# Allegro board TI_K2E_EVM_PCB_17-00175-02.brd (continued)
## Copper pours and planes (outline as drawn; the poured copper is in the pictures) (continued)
GND on TOP: 173.58,51.54 174.04,51.08 174.04,49.23 173.6,48.79 170.77,48.79 170.38,49.17 170.38,51.23 170.69,51.54
GND on TOP: 130.68,17.35 130.68,12.75 135.25,12.75 135.25,17.35
GND on TOP: 135.64,57.23 135.24,57.62 135.24,59.68 135.25,59.69 135.25,62.38 136.04,63.17 159.66,63.17 159.92,62.92 159.92,60.58 159.72,60.38 153.8,60.38 152.49,61.68 144.73,61.68 144.59,61.82 143.66,61.82 143.52,61.68 139.56,61.68 139.19,61.32 139.19,60.07 139.55,59.72 141.05,59.72 141.12,59.64 141.12,57.71 141.1,57.68 140.71,57.68 140.25,57.23
GND on TOP: 175.81,31.86 175.81,33.26 175.68,33.39 173.9,33.39 173.63,33.12 173.63,31.93 173.82,31.74 175.68,31.74
GND on TOP: 124.21,100.14 124.21,97.14 124.37,96.98 125.34,96.98 125.66,97.3 125.66,100.13 125.43,100.36 124.42,100.36
GND on TOP: 168,53.57 170.18,53.57 171.5,54.89 171.5,54.97 171.81,55.27 172.69,55.27 172.9,55.07 172.9,53.34 171.68,52.12 170.18,52.12 169.29,51.23 169.29,50.06 169.04,49.81 165.79,49.81 165.48,50.11 165.48,50.98 165.6,51.09 167.14,51.09 167.74,51.69 167.74,53.31
GND on TOP: 39.24,9.02 41.35,9.02 41.78,8.59 41.78,2.54 41.27,2.03 31.24,2.03 30.48,2.79 30.48,8.26 30.61,8.38 38.61,8.38
GND on TOP: 48.51,31.24 47.37,31.24 47.12,31.5 47.12,33.15 47.37,33.4 48.39,33.4 48.64,33.15 48.64,31.37
GND on TOP: 157.96,68.05 157.66,68.35 157.66,69.8 157.96,70.1 158.22,70.1 158.53,70.41 163.14,70.41 163.54,70.02 163.54,64.79 162.88,64.14 138.05,64.14 137.67,64.52 137.67,66.67 137.79,66.8 144.27,66.8 145.29,65.79 159.46,65.79 159.61,65.94 159.61,67.61 159.18,68.05
GND on TOP: 42.42,30.35 41.15,30.35 40.84,30.66 40.84,32.72 41.27,33.15 42.29,33.15 42.55,32.89 42.55,30.48
GND on TOP: 108.48,121.87 108.61,122 108.61,122.33 108.46,122.48 107.52,122.48 107.31,122.68 106.93,122.68 106.81,122.56 106.81,121.55 106.93,121.43 107.29,121.43 107.73,121.87
GND on TOP: 158.37,34.65 158.37,31.7 158.57,31.5 161.8,31.5 162.79,32.49 162.79,34.06 163.08,34.35 163.08,35.17 163.02,35.23 158.95,35.23
GND on BOTTOM: 127.38,8.89 127.38,4.45 127.13,4.19 125.73,4.19 125.48,4.45 125.48,8.76 125.73,9.02 127.25,9.02
GND on BOTTOM: 28.96,68.83 25.4,68.83 25.27,68.96 25.27,70.23 25.53,70.48 29.21,70.48 29.44,70.26 29.44,69.32
GND on BOTTOM: 77.88,33.4 79.12,33.4 79.25,33.27 79.25,31.34 79.22,31.32 79.6,30.94 80.19,30.94 80.49,30.63 80.49,29.44 80.24,29.18 78.11,29.18 77.72,29.57 77.72,33.25
GND on BOTTOM: 49.07,39.34 50.6,39.34 50.88,39.06 50.88,37.85 50.7,37.67 47.85,37.67 47.78,37.74 47.78,39.24 47.88,39.34 49.07,39.34
GND on BOTTOM: 114.3,32.36 115.9,32.36 116.1,32.56 116.94,32.56 117.17,32.33 117.17,30.99 116.94,30.76 114.33,30.76 114.07,31.01 114.07,32.13
GND on BOTTOM: 98.45,15.27 98.45,9.78 103.1,9.78 103.1,15.27
GND on BOTTOM: 147.24,32.92 147.68,32.49 147.68,31.57 147.42,31.32 141.22,31.32 141.12,31.42 141.12,32.64 141.4,32.92
GND on BOTTOM: 63.2,11.43 63.2,6.1 66.4,6.1 66.4,11.43
GND on BOTTOM: 120.29,31.67 118.11,31.67 117.91,31.47 117.91,30.73 118.21,30.43 120.14,30.43 120.42,30.71 120.42,31.55
GND on BOTTOM: 129.41,32.38 129.41,28.22 129.01,27.81 127.69,27.81 127.53,27.97 127.53,32.08 127.94,32.49 129.31,32.49
GND on BOTTOM: 151.49,26.67 151.49,26.11 151.69,25.91 155.45,25.91 155.6,26.06 155.6,26.67 155.35,26.92 151.74,26.92
GND on BOTTOM: 29.95,75.95 31.14,75.95 31.52,75.56 31.52,74.22 31.42,74.12 29.72,74.12 29.67,74.17 29.67,75.67
GND on BOTTOM: 30.99,71.04 29.49,71.04 29.26,71.27 29.26,72.62 29.36,72.72 31.06,72.72 31.12,72.67 31.11,71.17
GND on BOTTOM: 135.7,99.88 139.85,99.88 139.92,99.95 139.92,100.95 139.8,101.06 138.84,101.06 138.08,101.82 135.56,101.82 135.55,101.83 135.31,101.83 135.24,101.75 135.24,100.35
GND on BOTTOM: 176.45,106.55 174.98,106.55 174.7,106.83 174.7,107.26 174.85,107.42 176.53,107.42 176.66,107.29 176.66,106.76
GND on BOTTOM: 47.73,81.56 47.73,82.78 47.6,82.91 47.6,83.74 47.85,84 49.12,84 49.28,83.85 49.28,81.28 49.15,81.15 48.13,81.15
GND on BOTTOM: 54.15,3.38 54.15,1.8 53.9,1.55 52.35,1.55 51.54,2.36 51.54,3.15 51.66,3.28 52.07,3.28 52.53,3.73 52.53,5.23 53.14,5.84 58.04,5.84 58.19,5.69 58.19,4.19 57.71,3.71 57.71,3.51 57.63,3.43 56.97,3.43 56.9,3.51 56.9,3.84 57.23,4.17 57.23,4.67 57.02,4.88 56.69,4.88 56.54,4.72 56.54,4.5 56.44,4.39 55.17,4.39
GND on BOTTOM: 117.09,36.98 117.54,37.43 118.81,37.43 119,37.62 120.4,37.62 120.78,38 120.78,38.51 120.65,38.63 120.65,40.79 120.4,41.05 117.35,41.05 116.23,39.93 109.37,39.93 109.09,39.65 109.09,37.36 109.47,36.98
GND on BOTTOM: 142.44,58.12 142.44,56.13 144.42,56.13 144.42,58.12
GND on BOTTOM: 154.31,71.53 154.31,69.49 156.36,69.49 156.36,71.53
GND on BOTTOM: 100.61,25.86 100.77,25.69 100.77,24.63 100.66,24.51 97.13,24.51 96.93,24.71 96.93,25.73 97.05,25.86
GND on BOTTOM: 82.25,96.93 82.25,92.81 86.36,92.81 86.36,96.93
GND on BOTTOM: 147.75,38.56 147.85,38.66 147.85,39.67 147.75,39.78 144.7,39.78 144.6,39.67 144.6,38.66 144.7,38.56
GND on BOTTOM: 25.65,79.48 25.65,80.85 25.76,80.95 26.7,80.95 26.85,80.8 26.85,79.5 26.7,79.35 25.78,79.35
GND on BOTTOM: 27.61,77.22 28.85,77.22 29.03,77.04 29.03,75.87 28.78,75.62 27.69,75.62 25.91,75.62 25.58,75.95 25.58,77.32 25.6,77.34 25.68,77.34 25.81,77.22
GND on BOTTOM: 111.91,25.86 112.08,25.69 112.08,24.63 111.96,24.51 108.43,24.51 108.23,24.71 108.23,25.73 108.36,25.86
GND on BOTTOM: 124.21,32.89 123.67,33.43 122.76,33.43 122.73,33.4 122.73,31.01 122.99,30.76 126.11,30.76 126.26,30.91 126.26,32.77 126.14,32.89
GND on BOTTOM: 143.28,82.02 143.28,80.29 145.01,80.29 145.01,82.02
GND on BOTTOM: 149.99,15.62 149.99,14.2 150.22,13.97 153.87,13.97 154.05,14.15 154.05,15.62 153.92,15.75 150.11,15.75
GND on BOTTOM: 18.57,60.17 15.8,60.17 15.75,60.22 15.75,61.49 15.95,61.7 17.48,61.7 17.75,61.98 18.47,61.98 18.9,61.54 18.9,60.5
GND on BOTTOM: 111.12,49.07 110.57,49.07 110.24,49.4 110.24,64.14 110.52,64.41 111.33,64.41 111.76,63.98 111.76,54.05 111.56,53.85 111.56,49.83 111.3,49.58 111.3,49.25
GND on BOTTOM: 149.22,89.41 149.45,89.18 149.86,89.18 149.96,89.28 149.96,94.77 149.81,94.92 149.4,94.92 149.22,94.74
GND on BOTTOM: 143.38,14.99 143.51,14.86 144.65,14.86 144.78,14.99 144.78,18.03 144.65,18.16 142.75,18.16 142.62,18.03 142.62,16.38 142.24,16 141.35,16 141.05,15.7 139.67,15.7 139.57,15.6 139.57,15.04 139.62,14.99
GND on BOTTOM: 25.43,22.25 18.26,22.25 17.65,22.86 17.65,24 17.91,24.26 23.11,24.26 23.24,24.13 25.65,24.13 26.16,23.62 26.16,22.99
GND on BOTTOM: 112.7,131.7 112.7,126.7 117.91,126.7 117.91,131.7
GND on BOTTOM: 31.01,80.87 31.01,79.81 30.96,79.76 29.01,79.76 28.73,80.04 28.73,80.92 29.08,81.28 30.61,81.28
GND on BOTTOM: 145.69,19.3 144.3,19.3 142.57,21.03 141.53,21.03 140.49,22.07 139.04,22.07 138.84,22.28 138.84,23.04 139.01,23.22 140.39,23.22 140.97,22.63 144.3,22.63 144.5,22.83 144.5,25.1 144.63,25.22 145.8,25.22 145.85,25.17 145.85,22.07 145.97,21.95 145.97,19.58
GND on BOTTOM: 23.01,19.05 20.7,19.05 20.07,19.68 17.65,19.68 17.4,19.94 17.4,21.21 17.91,21.72 22.61,21.72 25.57,18.76 29.78,18.76 29.92,18.62 29.92,16.89 29.79,16.76 26.8,16.76 26.16,17.4 24.38,17.4 23.75,18.03 23.75,18.31
GND on BOTTOM: 141.43,10.9 141.43,9.37 141.76,9.04 147.22,9.04 147.47,9.3 147.47,9.6 147.83,9.96 148.49,9.96 148.64,10.11 148.64,10.82 148.54,10.92 147.42,10.92 147.02,10.52 145.75,10.52 145.24,11.02 141.55,11.02
GND on BOTTOM: 61.37,29.29 57.2,29.29 56.77,29.72 56.77,35.84 57.12,36.2 61.67,36.2 61.82,36.04 61.82,29.74
GND on BOTTOM: 136.49,89.52 136.38,89.62 131.74,89.62 131.74,89.62 130.75,89.62 130.7,89.57 130.7,88.19 130.76,88.13 135.95,88.13 136.48,88.66 136.48,89.51
GND on BOTTOM, L3_SIG1, L5_SIG2, L8_SIG3, L10_SIG4: 64.36,96.93 64.36,92.81 68.48,92.81 68.48,96.93
GND on L2_GND1: outline of 106 points within 1.02,1.02 179.58,147.48
GND on L5_SIG2: 82.25,96.93 82.25,93.4 82.83,92.81 86.36,92.81 86.36,96.93
GND on L6_GND2: outline of 106 points within 1.02,1.02 179.58,147.48
GND on L7_GND3: outline of 106 points within 1.02,1.02 179.58,147.48
GND on L8_SIG3: 101.65,1.02 101.65,1.75 102.13,2.24 102.13,6.22 102.31,6.4 104.67,6.4 106.55,4.52 106.55,1.85 105.72,1.02
GND on L11_GND4: outline of 106 points within 1.02,1.02 179.58,147.48
GND_3 on TOP: 107.56,123.08 107.72,122.91 108.69,122.91 108.9,123.13 108.9,124.02 108.73,124.19 107.69,124.19 107.56,124.05
GND_LAN on TOP: 176.25,33.35 176.45,33.55 178.59,33.55 179.02,33.12 179.02,11.28 179.01,11.26 179.01,9.41 178.66,9.07 173.79,9.07 173.08,9.78 173.08,12.22 173.99,13.13 173.99,27.43 173.1,28.32 173.1,30.81 173.46,31.17 176.05,31.17 176.25,31.37
GND_LAN on L8_SIG3: 154.74,30.25 175.18,30.25 176.17,29.26 176.17,8.59 175.87,8.28 154,8.28 151.61,10.67 151.61,18.41 152.27,19.08 152.27,27.79
GND_USB on BOTTOM: 172.52,141.2 172.69,141.02 174.8,141.02 175.01,140.82 175.01,131.22 175.16,131.06 179.27,131.06 179.53,131.32 179.53,141.66 178.99,142.19 173.66,142.19 173.43,142.42 172.62,142.42 172.52,142.32
VCC0V75 on TOP: 107.9,26.01 95.28,26.01 95,26.29 95,28.12 96.6,29.72 103.93,29.72 104.25,29.41 107.81,29.41 108.48,28.73 108.48,26.59
VCC0V75 on BOTTOM: 95.12,26.26 95,26.39 95,29.82 95.25,30.07 106.4,30.07 108.28,31.95 108.28,35.92 108.66,36.3 117.14,36.3 117.22,36.22 117.22,35.59 117.36,35.45 117.46,35.45 117.5,35.41 118.82,35.41 118.92,35.31 118.92,35.1 118.82,35 117.37,35 117.26,34.89 113.09,34.89 112.65,34.44 112.65,26.44 112.47,26.26
VCC0V75REF on BOTTOM: 122.2,38.53 122.2,36.25 122.07,36.12 121.06,36.12 120.93,36.25 120.93,37.64 121.18,37.9 121.18,41.33 121.44,41.58 123.09,41.58 123.34,41.33 123.34,39.04 123.09,38.79 122.45,38.79
VCC0V85 on TOP (solid shape): 124.28,21.64 124.28,19.1 124.02,18.84 107.15,18.84 106.81,19.18 106.81,21.84 107.34,22.38 123.55,22.38
VCC0V85 on BOTTOM: 34.14,52.76 32.13,52.76 32.03,52.86 32.03,55.65 32.21,55.83 34.11,55.83 34.26,55.68 34.26,52.88
VCC0V85 on BOTTOM: 28.93,81.94 28.7,82.17 28.7,82.8 29.08,83.19 31.95,83.19 32.36,82.78 32.36,81.92 32.23,81.79 31.75,81.79 31.6,81.94
VCC0V85 on L9_PWR2: 124.92,18.24 124.92,13.94 123.95,12.98 119.99,12.98 115.87,17.09 81.48,17.09 80.7,16.31 80.7,11.61 79.64,10.55 69.74,10.55 69.19,11.1 69.19,15.27 68.28,16.18 29.82,16.18 28.96,17.04 28.96,53.49 24.61,57.84 24.61,80.05 27.37,82.82 29.2,82.82 29.85,82.18 29.85,79.12 29.84,79.12 29.84,75.56 28.32,74.04 28.32,59.78 29.57,58.52 35.36,58.52 37.34,56.54 37.34,55.12 35.23,53.01 32.18,53.01 31.62,52.45 31.62,47.37 32.45,46.55 38.8,46.55 40.39,44.96 40.39,40.89 42.04,39.24 45.34,39.24 45.87,38.71 45.87,25.81 49.71,21.97 55.88,21.97 56.26,21.59 56.97,21.59 57.35,21.97 75.23,21.97 80.64,27.38 129.34,27.38 130.33,26.39 130.33,23.65
VCC1V5 on TOP: 146.94,67.69 142.24,67.69 142.11,67.56 138.3,67.56 137.79,68.07 137.79,71.88 138.18,72.26 146.99,72.26 147.04,72.21 147.04,67.79
VCC1V5 on BOTTOM: 109.37,50.01 109.37,61.37 109.12,61.62 109.12,62.56 109.37,62.81 109.37,64.77 109.14,65 107.31,65 107.09,64.77 107.09,59.59 107.67,59 107.67,58.04 107.09,57.45 107.09,50.09 107.29,49.89 109.25,49.89
VCC1V5 on BOTTOM: 116.81,32.92 117.13,33.24 117.12,33.25 117.12,34.29 116.97,34.44 113.21,34.44 113.08,34.31 113.08,32.74 113.16,32.66 113.92,32.66 114.17,32.92
VCC1V5 on L9_PWR2: 78.71,28.4 76.4,30.71 76.4,38.18 69.9,44.68 69.9,52.02 69.72,52.2 69.42,52.2 69.37,52.25 69.37,69.7 69.44,69.77 69.7,69.77 69.9,69.98 69.9,74.37 69.55,74.72 69.55,76.6 72.82,79.88 72.82,82.02 73.58,82.78 77.19,82.78 78.36,83.95 87.76,83.95 91.69,87.88 91.69,88.77 93.47,90.55 93.47,92.33 94.23,93.09 131.06,93.09 135.89,88.27 135.89,76.58 137.54,74.93 139.95,74.93 140.59,74.3 140.59,58.55 140.34,58.29 130.05,58.29 128.78,57.02 128.78,37.72 130.56,35.94 130.56,28.83 130.12,28.4
VCC1V8 on TOP (solid shape): 124.08,6.99 124.08,5.01 123.88,4.8 107.46,4.8 107.31,4.95 107.31,6.83 107.41,6.92 112.47,6.92 112.76,7.21 123.85,7.21
VCC1V8 on TOP: 159.56,50.9 160.48,50.9 160.6,51.03 160.6,52.22 160.48,52.35 159.46,52.35 158.97,51.85 157.34,51.85 157.15,51.66 157.15,50.22 157.23,50.14 157.78,50.14 157.91,50.27 157.91,50.95 158.1,51.14 159.32,51.14
VCC1V8 on TOP: 49.02,33.91 45.21,33.91 45.09,34.04 45.09,35.13 45.36,35.41 48.97,35.41 49.15,35.23 49.15,34.04
VCC1V8 on TOP: 152.45,35.56 150.75,35.56 150.62,35.69 150.62,37.08 150.83,37.29 151.99,37.29 152.17,37.47 152.53,37.47 152.73,37.26 152.73,35.84
VCC1V8 on BOTTOM: 151,19.81 149.73,19.81 149.61,19.94 149.61,21.21 149.86,21.46 150.88,21.46 151.13,21.21 151.13,19.94
VCC1V8 on BOTTOM: 31.8,70.38 31.93,70.51 33.05,70.51 33.12,70.43 33.12,68.99 32.84,68.71 30.25,68.71 29.92,69.04 29.92,70.21 30.1,70.38 31.7,70.38
VCC1V8 on BOTTOM: 50.67,40.13 50.9,40.36 50.9,41.78 50.77,41.91 48.39,41.91 47.6,41.12 47.6,40.41 47.88,40.13
VCC1V8 on BOTTOM: 32.31,59.18 34.04,59.18 34.29,58.93 34.29,56.31 34.11,56.13 32.21,56.13 32.05,56.29 32.05,58.93
VCC1V8 on BOTTOM: 75.01,83.97 73.89,82.85 73.05,82.85 72.87,83.03 72.87,83.52 73.48,84.12 73.48,84.63 75.36,86.51 77.14,86.51 77.32,86.33 77.32,84.53 76.76,83.97
VCC1V8 on BOTTOM: 81.15,62.2 81.15,63.53 81.43,63.81 82.96,63.8 83.08,63.68 83.08,62.15 82.96,62.03 81.33,62.03
VCC1V8 on L5_SIG2: 18.75,81.71 19.68,82.65 23.29,82.65 23.75,82.19 23.75,81.71 23.01,80.98 23.01,79.2 23.9,78.31 29.84,78.31 30.19,77.97 30.19,77.15 31.17,76.17 31.17,70.05 31.7,69.52 31.7,65.56 30.84,64.69 30.84,58.93 31.65,58.12 33.71,58.12 34.44,57.38 34.44,55.19 36.53,53.11 44.32,53.11 46.05,51.38 46.05,37.19 47.68,35.56 49.35,35.56 56.06,28.85 72.8,28.85 77.42,24.23 77.42,9.78 77.69,9.51 78.4,9.51 79.97,11.09 79.97,13.88 81.64,15.54 81.64,17.75 82.96,19.08 105.28,19.08 108.46,22.25 119.1,22.25 124.87,28.02 124.87,35.59 125.98,36.7 125.98,46.33 130.92,51.27 149.52,51.27 150.55,52.3 157.91,52.3 158.52,51.69 158.52,40.67 152.58,34.72 152.58,20.73 152.54,20.69 152.54,11.32 143.05,1.83 118.19,1.83 117.98,2.03 117.98,3.43 117.63,3.78 114.66,3.78 114.38,3.51 114.38,2.11 114.1,1.83 30.91,1.83 28.98,3.76 28.98,7.11 27.71,8.38 23.9,8.38 21.97,10.31 21.97,12.85 19.99,14.83 19.99,26.31 18.75,27.56
VCC1V8 on L5_SIG2: 84.2,61.39 81.43,61.39 80.85,61.98 80.85,64.36 81.61,65.13 81.61,69.6 79.98,71.22 78.94,71.22 73.1,77.06 73.1,84.89 74.83,86.61 77.17,86.61 84.02,79.76 84.02,66.85 84.38,66.5 84.38,61.57
VCC1V8 on L8_SIG3: 69.01,69.14 66.09,69.14 65.94,69.29 65.94,76.2 67.54,77.8 69.49,77.8 71.65,79.96 72.72,79.96 73.41,80.64 73.41,82.12 73.69,82.4 76.28,82.4 76.4,82.27 76.4,81.53 73.79,78.92 72.19,78.92 69.27,76 69.27,69.39
VCC1V8 on L9_PWR2: 73.15,83.19 73.03,83.31 73.03,87.5 71.37,89.15 56.21,89.15 54.64,87.58 53.21,87.58 51.77,89.03 49.28,89.03 48.95,89.36 48.95,92.79 48.13,93.6 44.91,93.6 43.18,91.87 43.18,87.6 43.31,87.73 43.31,81.13 50.69,73.75 50.69,73.75 51.62,72.81 51.62,67.41 51.49,67.28 48.53,67.28 46.94,65.69 43.19,65.69 39.77,69.11 32.49,69.11 31.37,68 29.57,68 28.73,68.83 28.73,73.78 30.15,75.21 30.15,82.38 29.43,83.1 26.97,83.1 26.02,84.05 26.02,89.89 25.12,90.8 8.57,90.8 7.72,91.65 7.72,140.46 14.25,146.99 164.92,146.99 166.13,145.78 170.07,145.78 171.42,144.42 171.42,141.07 174.45,138.05 174.45,119.18 172.11,116.84 131.06,116.84 125.6,111.38 125.6,94.61 124.84,93.85 94.36,93.85 92.96,92.46 92.96,90.93 91.31,89.28 91.31,88.27 87.63,84.58 78.11,84.58 76.71,83.19
VCC1V8 on L10_SIG4: outline of 100 points within 25.4,25.43 134.52,78.66
VCC2V5 on TOP: 128.88,14.1 127.43,14.1 125.09,16.43 125.09,39.7 128.45,43.05 136.53,43.05 136.98,42.6 136.98,41.76 136.63,41.4 132,41.4 130.86,40.26 130.86,28.96 131.32,28.5 140.84,28.5 143.36,25.98 143.36,24.05 137.79,18.49 131.06,18.49 129.31,16.74 129.31,14.53
VCC2V5 on BOTTOM: 144.12,23.11 144.17,23.16 144.17,23.65 144.07,23.75 142.6,23.75 141.3,25.04 138.4,25.04 138.13,24.77 138.13,23.83 138.38,23.57 138.79,23.57 139.14,23.93 140.23,23.93 141.05,23.11
VCC2V5 on L3_SIG1: 148.18,8.03 144.35,11.86 144.35,16.71 141.94,19.13 139.93,19.13 138.18,20.88 138.18,24.97 138.28,25.07 149.53,25.07 155.14,30.68 170.41,30.68 173.99,27.1 173.99,23.85 173.46,23.32 168.96,23.32 167.56,21.92 167.56,17.63 168.2,16.99 173.33,16.99 173.91,16.41 173.91,8.28 173.66,8.03
VCC3_LCDBK on BOTTOM (solid shape): 84.82,144.42 84.82,140.25 84.25,139.67 82.19,139.67 81.75,140.12 81.75,144.55 82.21,145.01 84.24,145.01
VCC3V3_AUX on TOP: 79.12,1.14 78.74,1.52 78.74,2.79 79.38,3.43 81.53,3.43 82.3,2.67 89.03,2.67 89.69,3.33 89.69,6.78 89.76,6.86 94.64,6.86 94.84,6.65 94.84,1.88 94.11,1.14
VCC3V3_AUX on BOTTOM: 25.15,80.8 25.15,79.22 25.27,79.09 25.27,77.67 25.2,77.6 24.08,77.6 23.95,77.72 23.95,80.72 24.16,80.92 25.02,80.92
VCC3V3_AUX on BOTTOM: 82.19,138.91 84.15,138.91 84.48,138.58 84.48,136.91 84.28,136.7 82.25,136.7 82.04,136.91 82.04,138.76
VCC3V3_AUX on BOTTOM: 123.69,34.68 123.34,34.34 121.01,34.34 120.9,34.24 120.9,34.16 121.18,33.88 124.1,33.88 124.41,33.58 125.98,33.58 126.29,33.88 126.29,35.76 126.11,35.94 123.77,35.94 123.69,35.85
VCC3V3_AUX on BOTTOM: 72.82,89.59 74.12,89.59 74.42,89.89 74.42,91.06 74.17,91.31 72.9,91.31 72.77,91.19 72.77,89.64
VCC3V3_AUX on BOTTOM: 90.93,100.97 90.93,99.75 90.7,99.52 88.8,99.52 88.6,99.72 88.6,100.97 88.77,101.14 90.75,101.14
VCC3V3_AUX on BOTTOM: 148.06,19.13 146.91,19.13 146.43,19.61 146.43,23.14 146.15,23.42 146.15,23.65 146.25,23.75 148.16,23.75 148.41,23.5 148.41,19.48
VCC3V3_AUX on BOTTOM: 147.07,13.97 147.07,12.95 147.19,12.83 147.83,12.83 147.96,12.95 147.96,13.97 147.83,14.1 147.19,14.1
VCC3V3_AUX on L4_PWR1: outline of 155 points within 7.85,1.02 179.4,146.94
VCC3V3_AUX on L5_SIG2: 15.44,1.19 12.32,1.19 11.94,1.57 11.94,4.37 10.85,5.46 2.16,5.46 1.45,6.17 1.45,66.55 2.46,67.56 11.56,67.56 12.22,68.22 12.22,84.86 12.88,85.52 26.52,85.52 27.43,84.61 27.43,79.58 26.87,79.02 24.08,79.02 23.62,79.48 23.62,80.64 24.26,81.28 24.26,82.6 23.65,83.21 19.13,83.21 17.65,81.74 17.65,15.54 21.34,11.86 21.34,9.07 19.91,7.65 15.7,7.65 15.62,7.57 15.62,1.37
VCC3V3_AUX_F1 on BOTTOM: 90.88,97.23 90.73,97.08 88.09,97.08 87.71,97.46 87.71,97.87 87.1,98.48 81.08,98.48 80.72,98.12 80.72,91.74 81.1,91.36 87.25,91.36 87.68,91.8 87.68,96.82 87.76,96.9 88.85,96.9 88.98,96.77 88.98,91.54 87.58,90.14 86.44,90.14 85.98,90.6 84.2,90.6 83.77,90.17 80.37,90.17 79.38,91.16 79.38,94.67 80.21,95.5 80.21,99.03 80.37,99.19 88.09,99.19 88.77,98.5 90.78,98.5 90.88,98.4
VCC3V3_AUX_F2 on BOTTOM: 71.37,89.28 69.62,89.28 68.88,90.02 62.61,90.02 61.32,91.31 61.32,95.73 62,96.42 62,98.86 62.87,99.72 64.01,99.72 64.14,99.59 64.14,98.53 64.01,98.4 63.27,98.4 62.66,97.79 62.66,91.82 63.12,91.36 69.62,91.36 69.75,91.49 69.75,98.81 69.88,98.93 71.2,98.93 71.22,98.91 71.22,94.31 71.04,94.13 71.04,92.63 71.5,92.18 71.5,89.41
VCC3V3_MP on TOP: 109.35,137.67 109.63,137.39 110.62,137.39 111,137.77 111,143.26 110.87,143.38 109.47,143.38 109.35,143.26
VCC3V3_MP on L4_PWR1: 130.38,60.15 115.6,60.15 112.44,63.31 112.44,65.13 113.77,66.46 113.77,72.72 110.69,75.79 110.69,77.11 106.25,81.56 101.6,81.56 101.14,82.02 101.14,95.3 100.78,95.66 100.78,104.39 104.5,108.1 104.5,119.84 103.45,120.88 103.45,127.17 105.89,129.62 108.03,129.62 108.89,130.48 108.89,132.46 107.75,133.6 93.07,133.6 88.22,138.46 76.5,138.46 75.13,137.08 75.13,136.02 71.17,132.05 71.17,112.83 70,111.66 67.39,111.66 66.42,112.62 66.42,139.73 69.42,142.72 69.42,145.85 70.82,147.24 165.3,147.24 165.74,146.81 165.74,146.33 165.84,146.23 172.62,146.23 173.53,145.31 173.53,141.07 174.6,140 174.6,131.22 175.01,130.81 179.27,130.81 179.27,122.99 178.71,122.43 124.49,122.43 123.01,120.95 117.83,120.95 116.94,120.07 109.98,120.07 109.02,119.1 109.02,112.6 110.57,111.04 111.61,111.04 111.93,110.73 111.93,104.99 109.88,102.94 109.88,98.25 112.52,95.61 125.07,95.61 136.03,84.64 136.03,80.76 135.1,79.83 135.1,64.87
VCC3V3_MP_ALT on TOP: 124.54,139.88 124.84,139.57 124.84,133.73 125.09,133.48 126.62,133.48 127,133.86 127,139.45 127.33,139.78 127.33,141.5 127.29,141.54 121.32,141.54 120.27,140.49 120.27,137.79 120.52,137.54 121.92,137.54 122.11,137.73 122.11,139.64 122.35,139.88
VCC3V3_MP_ALT on L8_SIG3: 123.6,145.92 129.82,145.92 131.06,144.68 131.06,143.92 130.38,143.23 129.01,143.23 125.04,139.27 125.04,130.96 124.82,130.73 123.75,130.73 123.33,131.15 121.78,131.15 119.81,133.12 119.81,140.49 122.35,143.03 122.35,144.68
VCC3V3_PCIE on BOTTOM: 27.15,66.83 25.32,66.83 25.07,67.08 25.07,68.3 25.1,68.33 28.32,68.33 28.57,68.58 29.41,68.58 29.59,68.4 29.59,67.64 29.24,67.28 27.61,67.28
VCC3V3_PCIE on BOTTOM: 17.42,64.31 18.77,64.31 18.8,64.29 18.8,62.76 18.36,62.33 12.88,62.33 12.62,62.59 12.62,63.47 13.21,64.06 17.17,64.06
VCC5V on TOP: 151.24,60.1 153.34,60.1 153.5,59.94 155.34,59.94 155.4,59.99 159.23,59.99 159.61,59.61 159.61,56.46 158.3,55.14 151.26,55.14 151.22,55.18 151.22,60.08
VCC5V on TOP: 162.99,52.63 163.93,52.63 164.03,52.53 164.03,52.22 164.08,52.17 166.29,52.17 166.62,52.5 166.62,53.72 166.73,53.82 167.23,53.82 167.34,53.72 167.34,51.94 166.88,51.49 165.46,51.49 165.02,51.05 163.25,51.05 162.86,51.44 162.86,52.5
VCC5V on BOTTOM: 17.53,17.53 17.53,18.52 18.26,19.25 19.61,19.25 20.32,18.54 21.34,18.54 21.62,18.26 22.89,18.26 23.37,17.78 23.37,17.14 23.62,16.89 25.4,16.89 26.75,15.54 29.74,15.54 30,15.29 30,12.98 29.82,12.8 22.25,12.8
VCC5V on L5_SIG2: 171.4,31.24 155.55,31.24 155.02,31.78 155.02,35.64 159.59,40.21 159.59,53.09 159.56,53.11 142.24,53.11 141.17,52.04 138.48,52.04 134.7,55.83 134.7,62.64 138.94,66.88 162.93,66.88 173.05,56.76 173.05,32.89
VCC5V on L9_PWR2: 159.18,56.64 158.57,56.64 156.24,58.98 156.24,66.93 158.95,69.65 163.19,69.65 165.53,71.98 165.53,75.56 164.54,76.56 137.97,76.56 137.49,77.04 137.49,89.03 132.66,93.85 128.14,93.85 126.87,95.12 126.87,110.24 132.46,115.82 173.33,115.82 174.17,114.99 174.17,95.35 174.42,95.1 177.37,95.1 178.44,94.03 178.44,71.96 176.1,69.62 176.1,56.95 175.74,56.59 159.23,56.59
VCC12 on TOP (solid shape): 113.16,14.05 113.16,12.78 113.03,12.65 107.75,12.65 107.21,12.12 103.84,12.12 103.73,12.22 103.73,12.93 103.76,12.95 106.71,12.95 107.98,14.22 112.98,14.22
VCC12 on TOP (solid shape): 89.28,13.72 94.49,13.72 94.74,13.46 97.79,13.46 97.92,13.34 97.92,12.7 97.79,12.57 96.52,12.57 96.27,12.32 83.06,12.32 82.3,13.08 82.3,14.86 83.06,15.62 87.38,15.62
VCC12 on TOP: 62.56,9.27 62.71,9.42 62.71,11.58 62.64,11.66 61.82,11.66 61.72,11.56 51.84,11.56 51.59,11.81 43.46,11.81 43.15,11.51 43.15,4.72 43.94,3.94 49.78,3.94 50.9,5.05 52.91,5.05 53.37,5.51 53.37,8.15 54.48,9.27
VCC12 on TOP: 26.29,15.49 41.53,15.49 41.83,15.19 41.83,10.46 41.53,10.16 39.5,10.16 38.23,11.43 35.56,11.43 34.04,9.91 30.2,9.91 28.75,8.46 25.81,8.46 24.99,9.27 24.99,14.2
VCC12 on TOP: 129.06,129.92 129.97,129.92 130.18,129.72 130.18,129.06 130.02,128.91 128.93,128.91 128.78,129.06 128.78,129.64
VCC12 on TOP: 163.32,70.79 163.68,71.15 163.68,74.47 163.53,74.63 161.75,74.63 161.52,74.4 161.52,72.77 161.25,72.5 157.82,72.5 157.61,72.29 157.61,70.59 157.66,70.54 158.12,70.54 158.37,70.79
VCC12 on TOP: 135.46,56.85 135.1,56.49 135.1,53.16 135.25,53.01 137.03,53.01 137.26,53.24 137.26,54.86 137.53,55.13 140.96,55.13 141.17,55.35 141.17,57 141.15,57.02 140.59,57.02 140.41,56.85
VCC12 on BOTTOM: 25.78,25.15 22.99,25.15 22.61,24.77 17.78,24.77 17.53,25.02 17.53,26.92 17.78,27.18 25.15,27.18 26.04,26.29 26.04,25.4
VCC12 on L9_PWR2: 11.94,1.04 11.84,1.14 11.84,4.17 10.64,5.36 1.22,5.36 1.07,5.51 1.07,67.79 1.47,68.2 11.07,68.2 11.91,69.04 11.91,85.04 10.77,86.18 7.95,86.18 7.77,86.36 7.77,89.48 7.91,89.48 8.58,90.15 25.03,90.15 25.64,89.53 25.64,81.7 24.05,80.11 24.05,57.76 28.32,53.49 28.32,16.64 29.34,15.62 67.69,15.62 68.45,14.86 68.45,10.62 69.29,9.78 80.16,9.78 81.64,11.25 81.64,16.05 82.22,16.64 115.27,16.64 119.41,12.5 125.63,12.5 126.11,12.98 126.11,18.69 131.19,23.77 131.19,36.07 129.29,37.97 129.29,56.39 130.68,57.78 140.46,57.78 141.22,58.55 141.22,73.91 142.62,75.31 164.21,75.31 164.97,74.55 164.97,72.36 162.94,70.33 158.42,70.33 155.57,67.49 155.57,58.62 159.03,55.17 159.03,50.44 147.96,39.37 147.96,4.7 144.3,1.04 125.65,1.04 125.5,1.19 125.5,3.4 125.3,3.61 122.53,3.61 122.3,3.38 122.3,1.3 122.05,1.04
VCC12_AMC on TOP, BOTTOM, L5_SIG2, L8_SIG3, L10_SIG4: 15.75,1.65 15.75,7.06 16.1,7.42 27.48,7.42 28.02,6.88 28.02,1.63 27.69,1.3 16.1,1.3
VCC12_AMC on L4_PWR1: 12.27,1.02 11.84,1.45 11.84,4.09 10.62,5.31 1.57,5.31 1.04,5.84 1.04,67.72 1.52,68.2 11.35,68.2 12.75,66.8 18.34,66.8 19.53,65.61 19.53,59.26 20.65,58.14 20.65,23.04 22.68,21.01 26.77,21.01 30,17.78 30,1.07 29.95,1.02
VCCPLLA1B on TOP (solid shape): 69.6,104.37 69.6,103.48 69.24,103.12 69.24,100.86 69.11,100.74 68.81,100.74 68.8,100.73 68.8,97.91 68.73,97.84 68.55,97.84 68.53,97.86 68.53,98.91 68.52,98.92 68.31,98.92 68.3,98.91 68.3,97.87 68.27,97.84 68.07,97.84 68.04,97.87 68.04,104.55 69.42,104.55
VCCPLLA2B on TOP (solid shape): 87.48,104.55 87.48,103.68 87.15,103.35 87.15,100.18 86.69,99.72 86.69,97.94 86.61,97.86 86.49,97.86 86.42,97.94 86.42,98.95 86.39,98.98 86.21,98.98 86.19,98.97 86.19,97.93 86.12,97.86 85.99,97.86 85.92,97.93 85.92,98.92 86.11,99.11 86.11,104.14 86.54,104.57 87.45,104.57
VDD33 on BOTTOM: 29.77,76.45 29.53,76.7 29.53,77.38 29.29,77.62 25.6,77.62 25.55,77.67 25.55,78.87 25.6,78.92 27.53,78.92 27.94,79.32 32.59,79.32 32.97,78.94 32.97,76.58 32.84,76.45
VDD33 on BOTTOM: 49.99,81.25 49.99,83.79 50.15,83.96 51.07,83.96 51.08,83.97 51.27,83.78 51.27,80.1 51.19,80.02 49.52,80.02 49.48,80.06 49.48,80.75
VDD33 on L3_SIG1: 30.43,80.54 30.43,77.37 31.79,76.01 33.01,76.01 33.73,75.29 46.91,75.29 48.01,76.38 48.01,80.34 47.29,81.05 47.29,84.3 46.94,84.66 45.26,84.66 43.26,82.65 32.54,82.65
VDD33 on L5_SIG2: 59.59,66.37 58.01,66.37 57.89,66.24 57.89,65.15 57.78,65.05 49.56,65.05 49.33,64.82 39.55,64.82 37.06,67.31 35.71,67.31 34.34,68.68 32.36,68.68 32.21,68.53 32.21,65.13 33.73,63.6 35,63.6 35.64,62.97 46.3,62.97 46.58,63.25 59.39,63.25 59.66,63.53 59.66,66.29
VDD33 on L9_PWR2: 53.47,86.49 51.66,88.29 51.66,88.32 51.49,88.49 49.2,88.49 48.56,89.13 48.56,92.46 47.88,93.14 45.11,93.14 43.66,91.69 43.66,85.42 43.41,85.17 43.41,81.78 50.29,74.91 52.37,74.91 53.47,76.01
VDD33 on L10_SIG4: 33.86,67.67 33.86,75.59 32.28,77.17 32.28,78.26 31.11,79.43 28.12,79.43 27.91,79.22 27.91,77.65 28.07,77.5 28.98,77.5 29.26,77.22 29.26,67.26 29.74,66.78 32.97,66.78
VDD_USB_0 on L10_SIG4: 63.42,64.92 60.4,64.92 60.27,65.05 60.27,68 60.53,68.25 60.91,68.25 61.09,68.43 61.09,74.8 59.31,76.58 59.31,85.22 60.05,85.95 62.13,85.95 62.59,85.5 62.59,78.99 63.7,77.88 63.7,70.76 63.42,70.48 63.09,70.48 62.87,70.26 62.87,67.59 63.02,67.44 63.47,67.44 63.65,67.26 63.65,65.15
VDD_USB_1 on L5_SIG2: 64.39,66.34 64.44,66.29 64.44,57.84 64.29,57.68 40.23,57.68 39.8,58.12 39.8,59.28 40.42,59.91 47.97,59.91 48.34,60.27 62.23,60.27 62.69,60.73 62.69,66.32 62.71,66.34
VDDAHV on BOTTOM: 33.96,59.72 32.23,59.72 31.98,59.97 31.98,62.59 32.16,62.76 34.06,62.76 34.21,62.61 34.21,59.97
VDDAHV on L9_PWR2: 43.13,65.01 47.33,65.01 48.96,66.65 52.73,66.65 52.96,66.42 52.96,55.37 52.88,55.3 40.26,55.3 40.13,55.42 39.09,55.42 35.55,58.97 31.46,58.97 31.45,58.97 30.1,58.97 28.86,60.21 28.86,66.04 29.92,67.11 31.27,67.11 32.68,68.52 39.62,68.52
VDDALV on BOTTOM: 32.28,52.27 34.01,52.27 34.27,52.02 34.26,49.4 34.08,49.22 32.18,49.23 32.03,49.38 32.03,52.02
VDDALV on L9_PWR2: 52.86,45.9 54.86,47.9 54.86,54.31 55.04,54.48 55.35,54.48 55.4,54.53 55.4,56.97 55.32,57.05 55.04,57.05 54.86,57.23 54.86,57.48 55.07,57.68 55.35,57.68 55.42,57.76 55.42,58.57 55.35,58.65 55.02,58.65 54.86,58.8 54.86,59.13 55.02,59.28 55.32,59.28 55.4,59.36 55.4,60.99 55.35,61.04 55.07,61.04 54.86,61.24 54.86,61.49 55.04,61.67 55.32,61.67 55.42,61.77 55.42,62.53 55.32,62.64 55.04,62.64 54.86,62.81 54.86,63.12 55.04,63.3 55.3,63.3 55.42,63.42 55.42,64.14 55.32,64.24 55.04,64.24 54.86,64.41 54.86,64.69 55.04,64.87 55.32,64.87 55.42,64.97 55.42,65.74 55.32,65.84 55.04,65.84 54.86,66.01 54.86,66.32 55.02,66.47 55.32,66.47 55.42,66.57 55.42,67.34 55.32,67.44 54.97,67.44 54.86,67.54 54.86,68.17 54.79,68.25 53.31,68.25 53.16,68.1 53.16,54.74 53.09,54.66 50.06,54.66 49.66,55.07 44.3,55.07 43.05,53.82 36.81,53.82 35.31,52.32 32.64,52.32 32.21,51.89 32.21,47.8 32.99,47.02 39.37,47.02 40.49,45.9
VDDPLL0 on BOTTOM: 80.62,63.7 80.62,62.26 80.39,62.03 78.89,62.03 78.77,62.15 78.77,63.68 78.89,63.8 80.52,63.8
VDDPLL0 on L8_SIG3: 69.9,55.91 69.72,56.08 69.34,56.08 69.09,56.34 68.4,56.34 67.51,57.23 67.51,65.56 67.79,65.84 68.94,65.84 69.11,66.01 69.11,68.73 69.34,68.96 71.42,68.96 71.65,68.73 71.65,66.78 73.38,65.05 80.01,65.05 80.67,64.39 80.67,63.3 79.04,61.67 72.54,61.67 70.82,59.94 70.82,57.12 70.92,57.02 71.53,57.02 71.65,56.9 71.65,53.95 71.37,53.67 70.05,53.67 69.9,53.82
CVDD on TOP: 63.83,28.65 63.83,14.94 63.88,14.88 66.88,14.88 67.11,15.11 69.72,15.11 70.43,15.82 70.43,17.48 70.51,17.55 76.16,17.55 76.27,17.66 76.27,35.97 76.07,36.17 63.07,36.17 62.8,35.9 62.8,29.69
CVDD on BOTTOM: 63.35,29.29 62.94,29.69 62.94,36.04 63.22,36.32 73.38,36.32 73.41,36.3 73.41,29.95 72.75,29.29
CVDD on L3_SIG1: 45.39,37.49 55.52,47.62 55.52,74.73 54.74,75.51 54.74,87.05 56.54,88.85 70.89,88.85 72.57,87.17 72.57,78.21 69.24,74.88 69.24,47.52 75.36,41.4 75.36,23.09 74.83,22.56 49,22.56 45.39,26.16
CVDD on L4_PWR1: 72.16,88.65 72.57,88.24 72.57,78.21 69.24,74.88 69.24,47.52 75.97,40.79 75.97,23.7 74.19,21.92 23.39,21.92 21.34,23.98 21.34,58.37 20.12,59.59 20.12,65.74 18.75,67.11 12.9,67.11 11.86,68.15 11.86,86.79 12.01,86.94 43.28,86.94 44.98,88.65
CVDD on L6_GND2: 58.6,68.91 58.78,69.09 58.78,76.35 54.74,80.39 54.74,87.05 56.49,88.8 70.94,88.8 72.57,87.17 72.57,78.21 68.99,74.63 68.99,45.92 68.76,45.69 59.92,45.69 57.2,48.41 57.2,50.19 55.07,52.32 49.17,52.32 46.63,49.78 46.63,37.92 49.2,35.36 63.42,35.36 64.44,36.37 73.03,36.37 74.83,34.57 74.83,27.69 68.25,21.11 39.37,21.11 30.61,29.87 30.61,61.49 33.1,63.98 48.06,63.98 48.31,63.73 49.15,63.73 49.4,63.98 53.64,63.98 54.1,64.44 54.1,68.76 54.25,68.91
CVDD on L9_PWR2: 46.61,44.83 47.12,45.34 53.24,45.34 55.55,47.65 55.55,69.72 54.86,69.72 54.74,69.85 54.74,75.95 54.61,76.07 54.61,86.92 56.34,88.65 71.09,88.65 72.57,87.17 72.57,80 69.19,76.62 69.19,44.96 75.97,38.17 75.97,23.75 74.78,22.56 49.66,22.56 46.61,25.6
CVDD1 on TOP: 80.62,19.99 88.52,19.99 89.38,19.13 89.38,18.75 89.36,18.72 89.36,17.7 89.53,17.53 94.46,17.53 94.74,17.81 94.74,20.6 91.52,23.83 80.59,23.83 80.44,23.67 80.44,20.17
CVDD1 on BOTTOM: 74.68,33.45 74.68,27.3 75.13,26.85 78.21,26.85 78.56,27.2 78.56,28.24 78.05,28.75 77.55,28.75 77.06,29.24 77.06,31.19 76.91,31.34 76.91,33.43 76.71,33.63 74.85,33.63
CVDD1 on L8_SIG3: 55.94,21.17 55.5,21.62 55.5,67.82 55.93,68.25 57.81,68.25 58.01,68.05 58.01,66.67 58.06,66.62 59.36,66.62 59.66,66.32 59.66,65.23 59.87,65.02 64.31,65.02 64.47,65.18 64.47,67.82 64.67,68.02 66.09,68.02 67.39,66.73 67.39,56.64 67.94,56.08 69.01,56.08 69.22,55.88 69.22,38.3 78.87,28.65 90.45,28.65 90.86,28.24 90.86,21.76 90.27,21.17
DDR_DVDD18 on TOP (solid shape): 142.37,93.7 142.37,91.06 142.09,90.78 139.73,90.78 139.6,90.91 139.6,93.7 139.83,93.93 142.14,93.93
DDR_DVDD18 on BOTTOM (solid shape): 144.65,98.7 144.65,96.27 141.2,92.81 141.2,91.06 141.12,90.98 139.62,90.98 138.94,91.67 138.94,93.37 142.98,97.41 142.98,97.87 142.62,98.22 142.44,98.22 142.37,98.3 142.37,98.78 142.49,98.91 144.45,98.91
PLL0_VDDA12 on BOTTOM (solid shape): 161.98,94.08 161.9,94.01 160.99,94.01 160.45,93.47 160.45,93.45 158.27,93.45 157.84,93.88 157.84,94.49 158.25,94.91 161.98,94.91
SATA_GND on TOP: 23.75,16.84 24.13,16.46 40.21,16.46 40.64,16.89 40.64,19.3 39.78,20.17 38.35,20.17 37.59,19.41 37.59,18.47 37.26,18.14 28.22,18.14 27.51,18.85 27.51,21.89 26.54,22.86 25.65,22.86 25.02,23.5 25.02,25.78 24.77,26.04 23.88,26.04 23.75,25.91
TRIP1 on TOP (solid shape): 164.92,146.91 164.92,143.89 164.8,143.76 154.13,143.76 153.64,144.25 153.64,147.04 154.38,147.78 164.06,147.78
TRIP2 on BOTTOM (solid shape): 39.55,148.16 39.55,147.24 39.37,147.07 36.25,147.07 35.97,146.79 35.97,144.45 35.71,144.2 34.44,144.2 34.09,144.55 34.09,146.86 33.86,147.09 29.49,147.09 29.39,147.19 29.39,148.16 29.44,148.21 39.5,148.21
TRIP2 on TOP: 37.36,146.56 34.37,146.56 34.14,146.33 34.14,144.22 34.32,144.04 37.49,144.04 37.85,144.4 37.85,146.08
USB0_0V85 on BOTTOM: 31.55,81.28 32.26,81.28 32.36,81.18 32.36,80.21 32.23,80.09 31.55,80.09 31.42,80.21 31.42,81.15
USB0_0V85 on L5_SIG2: 61.26,67.41 60.78,67.41 60.1,68.1 56.64,68.1 56.46,67.92 56.46,67.51 56.24,67.28 44.3,67.28 32.36,79.22 31.45,79.22 30.86,79.81 30.86,81.48 31.24,81.86 32.28,81.86 42.21,71.93 46.53,71.93 50.22,68.25 55.37,68.25 55.47,68.35 55.47,68.81 55.66,69 56.63,69 56.67,69.04 62.56,69.04 62.66,68.94 62.66,68.5 62.47,68.31 62.17,68.31
USB0_VDD3V3 on L5_SIG2: 60.25,66.73 60.25,67.28 60.1,67.44 56.57,67.44 56.3,67.17 56.3,66.76 56.18,66.65 49.25,66.65 48.82,66.22 48.21,66.22 47.68,66.75 44.04,66.75 34.77,76.02 32.44,76.02 31.52,75.11 31.52,72.47 35.79,68.2 39.42,68.2 39.71,67.91 39.71,66.56 41.15,65.13 48.79,65.13 49.35,65.68 57.15,65.68 57.25,65.79 57.25,66.4 57.4,66.55 60.07,66.55
USB0_VDDA33 on BOTTOM: 161.93,96.52 162.81,97.41 162.81,99.29 162.76,99.34 160.63,99.34 159.84,98.55 155.57,98.55 153.57,100.55 152.24,100.55 151.85,100.16 151.85,96.79 152.12,96.52
USB0VBUS on TOP: 163.09,35.71 163.75,35.05 165.74,35.05 167.59,36.91 167.59,38.48 167.31,38.76 166.09,38.76 165.79,38.46 165.79,36.73 165.48,36.42 164.41,36.42 163.04,37.8 154.97,37.8 154.69,38.07 154.69,42.04 154.81,42.16 154.81,42.93 154.69,43.05 153.39,43.05 153.14,42.8 153.14,36.88 153.29,36.73 157,36.73 157.4,36.32 157.4,35.18 157.48,35.1 158.24,35.1 158.85,35.71
USB1_0V85 on L8_SIG3: 63.3,67.06 61.54,67.06 61.11,67.49 61.11,74.47 63.88,77.24 63.88,80.98 65.23,82.32 72.59,82.32 72.87,82.04 72.87,80.67 72.42,80.21 69.42,80.21 65.2,76 65.2,69.29 65,69.09 64.64,69.09 64.24,68.68 64.24,68.53 63.98,68.28 63.83,68.28 63.42,67.87 63.42,67.18
USB1_VDD3V3 on L5_SIG2: 64.44,67.31 64.3,67.45 61.83,67.45 61.37,66.98 61.37,66.29 60.93,65.86 60.55,65.86 60.3,65.61 60.3,62.74 60.17,62.61 46.53,62.61 46.41,62.48 40.61,62.48 39.47,61.34 38.81,61.34 37.67,62.48 35.18,62.48 34.52,63.14 33.63,63.14 32.08,64.69 31.57,64.69 31.32,64.44 31.32,59.49 32.46,58.34 33.99,58.34 34.71,57.62 34.71,55.54 35.84,54.41 38.2,54.41 38.84,55.04 38.84,57.25 39.52,57.94 39.52,59.77 39.98,60.22 47.82,60.22 48.37,60.78 61.75,60.78 62.05,61.09 62.05,66.34 62.18,66.47 64.34,66.47 64.44,66.57
USB1VBUS on TOP: 156.08,52.7 156.08,50.93 156.21,50.8 156.59,50.8 156.72,50.93 156.72,51.77 157.19,52.24 158.05,52.24 159.82,54 161.77,54 164.67,56.9 166.29,56.9 166.65,56.54 166.65,55.47 166.88,55.24 171.2,55.24 171.7,55.75 175.51,55.75 175.77,56.01 175.77,56.16 175.54,56.39 173.23,56.39 172.85,56.77 168.55,56.77 167.59,57.73 163.27,57.73 160.82,55.28 159.37,55.28 156.92,52.83 156.21,52.83
USB_SHIELD on TOP: 176.17,67.41 176.17,52.6 175.01,51.44 175.01,48.92 174.27,48.18 170.78,48.18 169.49,49.48 167.36,49.48 166.17,48.29 166.17,46.45 169.04,43.58 169.04,37.74 166.5,35.2 166.5,33.45 167.59,32.36 170.15,32.36 172.29,34.49 177.7,34.49 179.2,35.99 179.2,67.51 178.82,67.89 176.66,67.89
USB_VBUS on TOP (solid shape): 164.57,140.18 164.57,139.24 164.29,138.96 164.01,138.96 163.83,138.79 163.83,137.39 163.75,137.31 163.63,137.31 163.55,137.39 163.55,140.21 163.65,140.31 164.44,140.31
USB_VBUS on BOTTOM: 168.15,130.84 168.3,130.99 168.3,133.07 168.1,133.27 166.85,133.27 166.66,133.08 166.66,130.9 166.73,130.84
USB_VBUS_R on BOTTOM: 170.31,135.46 172.26,135.46 172.39,135.33 172.39,134.52 171.73,133.86 171.2,133.86 170.69,133.35 170.69,130.99 170.54,130.84 168.81,130.84 168.71,130.94 168.71,133.27 168.15,133.83 168.15,134.37 168.28,134.49 169.34,134.49
USB_VIO on TOP (solid shape): 167.89,139.7 167.89,137.62 167.77,137.49 166.75,137.49 165.74,136.47 164.57,136.47 164.49,136.55 164.49,137.08 164.57,137.16 165.2,137.16 166.75,138.71 166.75,139.7 166.85,139.8 167.79,139.8
USB_VIO on BOTTOM: 162.18,141.68 162.18,140.97 163.07,140.08 166.47,140.08 166.73,139.83 166.73,137.77 166.95,137.54 167.82,137.54 167.89,137.62 167.89,138.15 167.72,138.33 167.72,140.97 167.59,141.1 163.96,141.1 163.09,141.96 162.46,141.96
VPP1V8 on TOP: 80.39,70.03 92.89,70.03 93.19,69.72 93.19,68.68 92.96,68.45 80.37,68.45 79.96,68.86 79.96,69.6
VPP1V8 on L5_SIG2: 79.6,64.87 80.75,66.01 80.75,69.65 80.54,69.85 78,69.85 75.54,67.39 70.21,67.39 69.98,67.16 69.98,66.88 69.75,66.65 68.76,66.65 68.33,67.08 68.33,67.97 68.15,68.15 67.92,68.15 67.49,67.72 67.49,67.61 67.31,67.44 66.95,67.44 66.85,67.54 66.85,67.74 66.45,68.15 66.12,68.15 65.91,67.94 65.91,65.13 66.17,64.87
XDS_1V2 on TOP (solid shape): 138.95,79.11 138.95,77.6 138.73,77.39 132.26,77.39 132.21,77.44 132.21,79.12 132.33,79.25 138.81,79.25
XDS_1V2 on BOTTOM: 163.35,95.12 163.35,92.68 163.5,92.53 164.97,92.53 165.13,92.68 165.13,95 164.87,95.25 163.47,95.25
XDS_1V2 on BOTTOM: 135.98,86.15 136.56,86.73 136.56,87.35 136.18,87.73 130.94,87.73 130.76,87.55 130.76,86.29 130.9,86.14 130.91,86.15
XDS_1V2 on L8_SIG3: 140.74,103.07 142.16,103.07 143.05,102.18 143.05,88.41 142.27,87.62 142.25,87.65 130.74,87.65 130.58,87.49 130.58,75.9 131.62,74.85 148.92,74.85 154.94,80.87 154.94,89.41 155.6,90.07 155.63,90.07 156.44,90.88 164.87,90.88 166.47,92.48 166.47,96.8 164.85,98.42 158.29,98.42 158.25,98.46 156.25,98.46 154.94,99.77 154.94,109.22 153.82,110.34 140.18,110.34 139.57,109.73 139.57,104.24
XDS_1V8 on TOP (solid shape): 146.46,93.78 146.46,91.16 146.05,90.75 143.43,90.75 143.08,91.11 143.08,93.6 143.48,94.01 146.23,94.01
XDS_1V8 on TOP (solid shape): 155.5,82.98 155.5,81.76 155.45,81.71 152.6,81.71 152.37,81.48 150.55,81.48 150.34,81.69 149.1,81.69 149.02,81.76 145.21,81.76 145.19,81.79 145.19,81.97 145.34,82.12 146.05,82.12 146.35,82.42 150.14,82.42 150.98,83.26 155.22,83.26
XDS_1V8 on L10_SIG4: 141.83,90.96 137.52,95.28 115.02,95.28 108.66,101.64 108.66,112.95 108.89,113.18 111.51,113.18 113.51,111.18 113.51,103.36 117.06,99.81 135.92,99.81 136.02,99.91 136.02,102.64 136.55,103.17 136.55,108.64 137.52,109.61 146.77,109.61 149.48,106.91 149.48,89.59 153.31,85.75 155.8,85.75 156.97,86.92 161.09,86.92 162.03,85.98 162.03,83.72 160.05,81.74 144.86,81.74 141.83,84.76
XDS_USB_GND on BOTTOM: 175.39,95.91 179.12,95.91 179.68,96.47 179.68,107.31 179.6,107.39 177.19,107.39 177.04,107.24 177.04,106.45 176.73,106.15 175.11,106.15 174.93,105.97 174.93,96.37
XDS_USB_VBUS on TOP (solid shape): 144.09,80.01 144.09,76.71 144.04,76.66 143.61,76.66 143.56,76.71 143.56,79.02 143.71,79.17 143.71,80.01 143.81,80.11 143.99,80.11
XDS_USB_VBUS on TOP (solid shape): 138.77,86.35 138.77,84.8 138.71,84.73 138.71,80.87 138.66,80.82 138.07,80.82 137.95,80.95 137.95,86.39 138,86.44 138.68,86.44
XDS_USB_VBUS on TOP (solid shape): 142.88,85.37 142.88,84 143.54,83.34 143.54,82.27 143.46,82.19 143.33,82.19 143.26,82.27 143.26,82.42 142.24,83.44 142.24,85.39 142.32,85.47 142.77,85.47
XDS_USB_VBUS on TOP (solid shape): 149.28,84.07 149.28,82.93 149.1,82.75 148.79,82.75 148.64,82.91 145.87,82.91 145.67,82.7 145.47,82.7 144.96,82.19 144.83,82.19 144.75,82.27 144.75,83.34 145.11,83.69 145.62,83.69 146.1,84.18 149.17,84.18
XDS_USB_VBUS on TOP (solid shape): 166.37,97 166.37,94.61 166.62,94.36 167.89,94.36 168.15,94.11 168.15,92.58 168.02,92.46 166.12,92.46 165.86,92.71 165.86,93.98 165.48,94.36 165.48,97.03 165.61,97.16 166.22,97.16
XDS_USB_VBUS on L3_SIG1: 153.14,95.99 153.14,85.7 154.51,84.33 164.59,84.33 167.92,87.66 167.92,100.76 170.99,103.84 173.99,103.84 174.35,104.19 174.35,108.86 173.86,109.35 169.29,109.35 168.22,108.28 166.29,108.28 161.85,103.84 161.85,100.99 159.69,98.83 159.69,94.18 159.38,93.88 156.59,93.88 155.37,95.1 155.37,95.89 154.94,96.32 153.47,96.32
XDS_VBUS on TOP: 168.02,97.66 168.28,97.41 168.28,94.61 169.04,93.85 169.04,92.71 169.29,92.46 170.18,92.46 170.31,92.58 170.31,94.92 169.57,95.66 169.57,98.15 169.72,98.3 171.73,98.3 172.34,98.91 172.34,100.23 172.06,100.51 170.56,100.51 169.9,101.17 169.9,102.18 168.96,103.12 165.81,103.12 165.71,103.02 165.71,101.63 165.96,101.37 167.11,101.37 167.61,101.88 168.12,101.88 168.48,101.52 168.48,99.87 168.02,99.42
XDS_VCC3V3 on TOP (solid shape): 145.49,89.38 145.49,88.24 145.31,88.06 144.35,88.06 144.27,87.99 144.27,85.6 144.02,85.34 144.02,84.33 143.89,84.2 143.38,84.2 143.26,84.33 143.26,87.25 143.38,87.38 143.38,89.56 143.46,89.64 145.24,89.64
XDS_VCC3V3 on BOTTOM (solid shape): 165.58,100.08 165.58,98.02 165.43,97.87 164.52,97.87 164.11,98.27 164.11,100.05 164.21,100.15 165.51,100.15
XDS_VCC3V3 on TOP: 121.78,98.41 121.83,98.35 123.1,98.35 123.4,98.66 123.4,101.07 123.27,101.2 122.04,101.2 121.78,100.94
XDS_VCC3V3 on BOTTOM: 135.74,97.04 137.07,97.04 137.34,97.3 137.34,98.03 138.19,98.88 139.81,98.88 139.97,98.72 139.97,98.29 141.76,98.29 141.98,98.52 141.98,99.35 141.82,99.51 141.51,99.51 141.39,99.39 135.59,99.39 135.46,99.26 135.46,97.32
XDS_VCC3V3 on L4_PWR1: 141.23,86.31 145.78,86.31 147.09,85 159.48,85 160.16,84.32 163.29,84.32 167.64,88.67 167.64,89.02 167.64,89.02 167.64,100.37 166.91,101.11 166.91,104.8 166.14,105.56 166.14,109.63 165.33,110.44 160.15,110.44 158.47,112.12 158.47,112.6 159.31,113.44 159.31,115.06 152.6,121.77 124.66,121.77 123.49,120.6 118.26,120.6 117.5,119.84 110.49,119.84 109.46,118.81 109.46,112.69 109.46,112.68 110.21,111.94 111.26,111.94 112.3,110.9 112.3,104.35 110.46,102.51 110.46,99.29 113.21,96.55 124.96,96.55 137.31,84.2 139.12,84.2
N14711749 on TOP: 111.38,134.59 111.58,134.39 112.24,134.39 112.42,134.57 112.42,137.19 112.78,137.54 112.78,139.45 112.7,139.52 111.61,139.52 111.38,139.29
N17204930 on BOTTOM: 148.46,17.02 148.34,16.89 148.34,16.38 148.46,16.26 153.67,16.26 153.8,16.38 153.8,16.64 153.67,16.76 153.29,16.76 153.03,17.02
N17705627 on TOP: 149.93,60.26 149.81,60.38 148.03,60.38 147.57,59.92 147.57,58.12 147.29,57.84 145.9,57.84 145.8,57.74 145.8,57.04 145.85,57 146.68,57 147.19,56.48 147.19,53.49 147.33,53.35 147.87,53.35 148.11,53.59 148.11,54.79 148.29,54.97 149.72,54.97 149.93,55.17
N17709291 on TOP: 149.45,67.26 150.75,67.26 151.21,67.72 151.21,69.52 151.49,69.8 152.88,69.8 153.06,69.98 153.06,70.51 152.93,70.64 151.94,70.64 151.59,70.99 151.59,73.38 150.78,74.18 150.78,74.51 150.75,74.55 149.88,74.55 149.8,74.46 149.8,73.8 149.17,73.17 149.17,67.54
N17726206 on TOP: 127.51,135.15 127.51,133.4 127.74,133.17 127.74,131.88 127.61,131.75 127.61,130.45 127.71,130.35 129.62,130.35 129.82,130.56 129.82,131.22 129.62,131.42 128.88,131.42 128.73,131.57 128.73,135.03 128.45,135.31 127.66,135.31
N17728755 on BOTTOM: 118.87,34.34 117.63,34.34 117.55,34.26 117.55,32.66 118.11,32.11 122.25,32.11 122.33,32.18 122.33,33.32 122.25,33.4 120.83,33.4 120.78,33.35 120.78,32.82 120.7,32.74 119.18,32.74 118.95,32.97 118.95,34.26
N17929864 on BOTTOM: 148.84,89.1 149.07,88.87 149.07,88.37 149.02,88.32 148.21,88.32 147.96,88.57 147.96,92.3 147.52,92.74 147.52,95.22 149.2,96.9 149.2,99.16 148.64,99.72 148.64,100.18 148.82,100.36 150.09,100.36 150.27,100.18 150.27,96.47 148.84,95.05
N17941980 on BOTTOM (solid shape): 161.29,109.73 161.29,106.43 161.14,106.27 159.97,106.27 159.66,106.58 159.66,109.73 160.07,110.13 160.88,110.13
N18360137 on BOTTOM: 151.82,23.5 152.53,23.5 152.65,23.62 152.65,24.51 152.78,24.64 155.55,24.64 155.65,24.74 155.65,25.35 155.54,25.46 151.57,25.46 151.51,25.4 151.51,24.64 151.64,24.51 151.64,23.67
N19617114 on TOP (solid shape): 143.54,80.04 143.54,79.27 142.52,78.26 142.14,78.26 141.4,77.52 140.54,77.52 140.45,77.6 140.45,79.27 140.69,79.5 142.62,79.5 143.23,80.11 143.46,80.11
N22090501 on TOP: 66.95,9.37 72.44,9.37 72.52,9.3 72.52,7.52 72.62,7.42 74.32,7.42 74.45,7.54 74.45,8.99 74.93,9.47 76.15,9.47 76.4,9.73 76.4,13.89 76.17,14.12 69.24,14.12 66.78,11.66 66.78,9.55
N22090505 on TOP (solid shape): 70.23,9.07 70.23,8.28 70.13,8.18 69.8,8.18 69.65,8.33 69.65,8.59 69.39,8.84 66.83,8.84 66.73,8.94 66.73,9.12 66.78,9.17 70.13,9.17
N22090506 on TOP: 72.06,8.99 72.06,8.36 71.98,8.28 70.61,8.28 70.59,8.31 70.59,8.89 70.71,9.02 72.03,9.02
N22090558 on TOP: 89.49,16.24 94.5,16.24 95.2,15.54 96.04,15.54 96.6,14.99 97.79,14.99 98.04,14.73 98.04,13.84 97.79,13.59 96.82,13.59 96.44,13.97 89.62,13.97 89.47,14.12 89.47,16.22
N22090583 on TOP (solid shape): 97.92,11.18 97.92,10.41 97.66,10.16 96.52,10.16 96.39,10.03 96.39,9.53 96.14,9.27 95.12,9.27 95,9.14 95,8.51 94.63,8.14 89.75,8.14 89.66,8.22 89.66,10.29 89.92,10.54 94.87,10.54 95.12,10.79 96.01,10.79 96.65,11.43 97.66,11.43
N22090598 on TOP (solid shape): 107.57,10.54 112.37,10.54 112.83,10.08 112.83,8.66 112.38,8.21 107.35,8.21 106.93,8.64 106.15,8.64 105.97,8.81 105.97,11.13 105.51,11.58 103.73,11.58 103.68,11.63 103.68,11.94 103.71,11.96 106.15,11.96
N22090602 on TOP (solid shape): 112.52,17.32 112.52,15.11 112.46,15.05 108.01,15.05 106.93,13.97 106.93,13.69 106.35,13.11 103.78,13.11 103.68,13.21 103.68,13.41 103.73,13.46 105.71,13.46 105.94,13.69 105.94,15.77 106.1,15.93 106.71,15.93 107.09,16.31 107.09,17.2 107.41,17.52 112.33,17.52
N22090668 on TOP: 74.93,8.71 75.31,9.09 76.68,9.09 76.99,8.79 76.99,6.02 76.78,5.82 74.98,5.82 74.93,5.87

Small or netless copper shapes (teardrops, artwork), in the pictures only: 1 on BOTTOM

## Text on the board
Ref Des/Silkscreen Bottom: 86 | 170 | z3 | K1 | L1 | PCA REV : 18_00175_02 | PCB REV : 17_00175_02 | 2 | AN1 | z4 | M1 | I1 | J1 | z2 | 1 | A | A33 | MADE IN INDIA | z1 | G1 | H1 | D1 | F1 | W | z7 | B1 | 19 | C1 | A1 | z6 | z5
User.Comments: UNLESS OTHERWISE SPECIFIED | ALL DIMENSIONS ARE IN | INCHES | DATE | REV | - | 1 | MILLIMETERS | CHANGES IN FAB DETAILS & IMPEDANCE DETAILS | INITIAL RELEASE | SIZE | SCALE | DRAWING TITLE | PART NUMBER | 1/1 | DESCRIPTION | REVISIONS | 04/03/2014 | SHEET | 1  OF | Library | QA & CAM | APPROVED | 04-03-2014 | 02 | D | eINFOCHIPS LIMITED | X
Ref Des/Silkscreen Top: Designed by: | TEXAS INSTRUMENTS | www.einfochips.com | TMDXEVM66AK2E | The Solutions people | 1 | 85 | Q | K | V | E | J | O | N | P | AA | H | L | AB | I | M | 59 | 71 | R | 2 | A | S | 72 | G | D | F | U | B | T | C | 62 | 61
DIMENSION: TYPICAL | 45+/-2 | NOTES: UNLESS OTHERWISE SPECIFIED. | 10. MINIMUM CONDUCTOR WIDTH:4.0 MILS | 11. THE PCB EDGE NEAR AMC CONNECTOR EDGE SHOULD BE AS SHOWN IN THE BELOW FIG. | 12. THE ALL DIMENSIONS ARE IN "MM [INCHES]". | REQUIREMENTS. | COPPER: AS PER STACKUP. | DIELECTRIC: FR4_ITEQ IT168G. | U.L. RATING: 94V-0 MINIMUM | 1. FABRICATE PER IPC-6012A CLASS 2. | 3. SURFACE FINISH:  ENIG | 6. 100% CONTINUITY TESTING USING DATABASE NETLIST SHALL BE PERFORMED, | VENDOR TO IDENTIFY TEST PASSED IN SECONDARY  SIDE. | 4. SOLDER MASK MATERIAL SHALL MEET ALL THE REQUIREMENTS OF | IPC-SM-840C AND SHALL BE GREEN IN COLOR AND APPLIED OVER BARE COPPER. | 7. VENDOR TO MARK DATE CODE AND LOGO  IN ETCH OR IN LEGEND. | 5. SILK SCREEN LEGEND TO BE APPLIED PER LAYER STACKUP USING WHITE | NON-CONDUCTIVE EPOXY INK. | 9. DIELECTRICS AND LINEWIDTHS MAY BE ADJUSTED TO MEET THE IMPEDANCE | 8. BOW AND TWIST SHALL NOT EXCEED 0.7% OF LONGEST SIDE . | MINIMUM SPACING:3.8 MILS | SCALE: NONE | FABRICATION DRAWING | TMDXEVM66AK2E | SENSITIVE ELECTRONIC DEVICES-CLASS 1 | CAUTION | SCORE DETAIL
PAGE_OUTLINE: 63.036 MILS +/-10% | PRIMARY SIDE, SILK SCREEN | PRIMARY SIDE, SOLDER MASK - 2 MILS | PRIMARY SIDE, LAYER 1     - 1.794 MILS | DIELECTRIC                - 3.596 MILS | INNER LAYER, LAYER 3      - 1.26 MILS | SECONDARY SIDE, LAYER 12    - 1.794 MILS | SECONDARY SIDE, SOLDER MASK - 2 MILS | GROUND LAYER, LAYER 2     - 1.26 MILS | DIELECTRIC                - 5 MILS | INNER LAYER, LAYER 5      - 1.26 MILS | DIELECTRIC                - 3.814 MILS | DIELECTRIC                - 4 MILS | GROUND LAYER, LAYER 7     - 1.26 MILS | DIELECTRIC                - 5.014 MILS | POWER LAYER, LAYER 4      - 1.26 MILS | GROUND LAYER, LAYER 6     - 1.26 MILS | INNER LAYER, LAYER 8      - 1.26 MILS | POWER LAYER, LAYER 9      - 1.26 MILS | INNER LAYER, LAYER 10     - 1.26 MILS | GROUND LAYER, LAYER 11    - 1.26 MILS | SECONDARY SIDE, SILK SCREEN | CAD | DATA | DO NOT MANUALLY | UPDATE | D | C | B | A | 8 | 7 | 6 | 5 | 4 | 3 | 2 | 1
User.8: A | K | J | D | G | F | E | B | C | L
User.9: A | z1 | C | D | E | B | L | H | J | Z | N | G | M | K | z2 | F
User.10: LAYER NO. | L10_SIG4 | L12_BOT | L03_SIG1 | L01_TOP | L05_SIG2 | L08_SIG3 | CONDUCTOR WIDTH | 4 MILS | 4.5 MILS | 6 MILS | 4.2 MILS | 7.5 MILS | SPACING | SINGLE ENDED | DIFFERENTIAL 90E | DIFFERENTIAL 100E | REFERENCE LAYER | L06_GND2 | L07_GND3 | L11_GND4 | L02_GND1 | IMPEDANCE +/-10% | 50 OHMS | 90 OHMS | 100 OHMS | NOT USED
User.11: DATE:04-03-2014 | DESIGNED AT:eINFOCHIPS LIMITED | PART NO/CARD REF:K2E_EVM_CARD | FILM LAYER: | COMPANY NAME : eINFOCHIPS  LIMITED | JOB NUMBER:EINF4982B | REV:02
User.12: 1 | PRIMARY SIDE
User.13: 2 | LAYER2
User.14: 3 | LAYER3
User.15: 4 | LAYER4
User.16: 5 | LAYER5
User.17: 6 | LAYER6
User.18: 7 | LAYER7
User.19: 8 | LAYER8
User.20: 9 | LAYER9
User.21: 10 | LAYER 10
User.22: 11 | LAYER 11
User.23: 12 | SECONDARY SIDE
User.24: FABRICATION LAYER
User.25: SOLDERMASK PRIMARY SIDE
User.26: SOLDERMASK SECONDARY SIDE
User.27: SOLDER PASTE PRIMARY SIDE
User.28: SOLDER PASTE SECONDARY SIDE
User.29: ASSEMBLY PRIMARY SIDE
User.30: ASSEMBLY SECONDARY SIDE
User.31: SILKSCREEN PRIMARY SIDE
User.32: SILKSCREEN SECONDARY SIDE
User.35: 0.4+/-0.1mm | 63.036Mil[1.60MM] | PCB THICKNESS
User.36: ESWAR
User.38: FIGURE | SIZE | 8.0 | 10.0 | 11.81 | 12.0 | 14.0 | 16.0 | 18.0 | 28.0 | 32.0 | 35.43 | 40.0 | 42.0 | 45.0 | 51.0 | 53.0 | 61.81 | 91.0 | 106.0 | 125.0 | 156.0 | 26.0 | 43.0 | 47.0 | 63.0 | 89.0 | 92.52 | 127.95 | 138.0 | 75.0x28.0 | 75.0x38.0 | 98.43x39.37 | 118.11x39.37 | 137.8x39.37 | 421.0x67.0 | DRILL CHART: TOP to BOTTOM | ALL UNITS ARE IN MILS | TOLERANCE | +3.0/-3.0 | +0.0/-0.0 | +2.0/-2.0 | +2.0/-0.0 | 18 MIL DRILLS ARE FOR PRESS FIT CONNECTOR WITH +/- 0 MILS TOLERANCES | PLATED | NON-PLATED | QTY | 2617 | 927 | 55 | 89 | 314 | 126 | 320 | 19 | 17 | 24 | 39 | 2 | 5 | 4 | 1
